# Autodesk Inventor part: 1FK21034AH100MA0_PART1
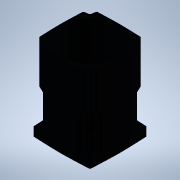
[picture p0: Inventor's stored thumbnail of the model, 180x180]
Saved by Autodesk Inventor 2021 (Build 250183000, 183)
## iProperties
Created: 2025-04
Part Number: 1FK21034AH100MA0_PART1
Material: Generic
Catalog Web Link: www.3dfindit.com
Description: -Servo synchronous motor
Document SubType Name: Modeling
Designer: psAdmin
Mass: 88.22 g
Surface Area: 399.791 cm^2
Volume: 88.22 cm^3
Density: 1 g/cm^3
Appearance: PSOLRGB-176-176-176
Category: PARTsolutions
Title: 1FK21034AH100MA0_PART1
Author: Cadenas PARTsolutions
Comments: Servo synchronous motor
Sending System: PARTsolutions
Preprocessor: ST-DEVELOPER v19.3
PSOL_IDENT_0: {$CADENAS_DATA/23d-libs/siemens_ag/_cat_/39/97/1fk21034ah100ma0.prj},213 {VTYP=3D},{NB=1FK21034AH100
PSOL_IDENT_1: MA0_PART1},{LINA=1FK21034AH100MA0_PART1},{NN=1FK21034AH100MA0_PART1},{NOPRJ=TRUE},{DATE=19.08.2025 1
PSOL_IDENT_2: 4:00:33},{GEOMDATE=30.07.2025 02:02:21},{VERSION=},{LINEID=10},{WBVAR=},{WBNUMERIC=}  {NB=1FK21034AH
PSOL_IDENT_3: 100MA0_PART1},{LINA=1FK21034AH100MA0_PART1},{KT=DUMMY},{PREVIEW=../../../_pool_/d3/78/p_d211_xx_0093
PSOL_IDENT_4: 4j.png},{DESCSHORT=SIMOTICS S-1FK2 HD, SINAMICS S210 3AC 400V-480V, 1.01 Nm, 4500 rpm},{DESCLONG=SIM
PSOL_IDENT_5: OTICS S-1FK2 HD servo motor M0=1.27 Nm; PN = 0.48 kW at nN=4500 rpm (380-480 V); PN = 0.3 kW at nN=2
PSOL_IDENT_6: 500 rpm (200-240 V); with holding brake; degree of protection IP64; cylindrical shaft D14 x 30 mm; a
PSOL_IDENT_7: bsolute encoder 22-bit + 12-bit multiturn (encoder AM22DQC); with OCC interface; plug size M17, rota
PSOL_IDENT_8: table; SIMOTICS S-1FK2 servomotorfor a wide range of uses in industrial environments. SIMOTICS S‑1FK
PSOL_IDENT_9: 2 servomotors are compact synchronous motors with a high dynamic performance that set themselves apa
PSOL_IDENT_10: rt as a result of their high power density, degree of protection and overload capability. The motors
PSOL_IDENT_11: are available in two variants: as High Dynamic variant (highest dynamic performance as a result of
PSOL_IDENT_12: the low intrinsic moment of inertia for applications demanding a high dynamic performance with low m
PSOL_IDENT_13: oved masses) - and as Compact variant (precise and stable closed-loop control for medium up to large
PSOL_IDENT_14: moved masses as a result of a medium intrinsic moment of inertia). SIMOTICSS‑1FK2 servomotors fully
PSOL_IDENT_15: exploit their strengths in a system with the SINAMICSS210 frequency converter and simple connection
PSOL_IDENT_16: using the one cable connection (OCC). Advantages include the short control and positioning times, f
PSOL_IDENT_17: ast and precise correction of disturbing quantities as well as stable control with a high dynamic pe
PSOL_IDENT_18: rformance. The servo motors can be configured to address a wide range of requirements. For example w
PSOL_IDENT_19: ith and without holding brake, IP64 or IP65 degree of protection, singleturn or multiturn absolute e
PSOL_IDENT_20: ncoders - to name just a few. Further, the servomotors are available in different shaft heights exte
PSOL_IDENT_21: nding from 20 to 100. A shaft sealing ring is available to achieve an IP65 degree of protection and
PSOL_IDENT_22: for subsequent mounting at the motor or as spare part. SIMOTICS - the optimum motor for each and eve
PSOL_IDENT_23: ry motion control application.},{INTNO=195125454019},{SUPPLIERALTNO=1FK2103-4AH10-0MA0},{MANUID=1FK2
PSOL_IDENT_24: 1034AH100MA0},{MANUNAME=Siemens},{MANUTYPEDESC=SYNCHRONOUS MOTOR 1FK2 HD 1,27 NM},{AAU732=SIMOTICS},
PSOL_IDENT_25: {AAO057=S-1FK2},{AAU734=SIMOTICS S-1FK2 HD servo motor M0=1.27 Nm; PN = 0.48 kW at nN=4500 rpm (380-
PSOL_IDENT_26: 480 V); PN = 0.3 kW at nN=2500 rpm (200-240 V); with holding brake; degree of protection IP64; cylin
PSOL_IDENT_27: drical shaft D14 x 30 mm; absolute encoder 22-bit + 12-bit multiturn (encoder AM22DQC); with OCC int
PSOL_IDENT_28: erface; plug size M17, rotatable;},{AAW338=SYNCHRONOUS MOTOR 1FK2 HD 1,27 NM},{AAO742=SIMOTICS},{AAO
PSOL_IDENT_29: 663=4034106444921},{NOCUPEROU=1},{PRICEQUANTITY=1},{QUANTITYMIN=1},{QUANTITYINT=1},{CTN=85015100},{C
PSOL_IDENT_30: OO=RO},{AAO676=1FK2103-4AH10-0MA0},{AAO677=Siemens AG},{ORDERUNIT=C62},{CONTENTUNIT=C62}
NB: 1FK21034AH100MA0_PART1
NT: Servo synchronous motor
NBSYN: $MANUID._PART1
LINA: 1FK21034AH100MA0_PART1
CATALOG: SIEMENS
PREVIEW: ../../../_pool_/d3/78/p_d211_xx_00934j.png
DESCSHORT: SIMOTICS S-1FK2 HD, SINAMICS S210 3AC 400V-480V, 1.01 Nm, 4500 rpm
DESCLONG: SIMOTICS S-1FK2 HD servo motor M0=1.27 Nm; PN = 0.48 kW at nN=4500 rpm (380-480 V); PN = 0.3 kW at nN=2500 rpm (200-240 V); with holding brake; degree of protec
INTNO: 195125454019
SUPPLIERALTNO: 1FK2103-4AH10-0MA0
MANUID: 1FK21034AH100MA0
MANUNAME: Siemens
MANUTYPEDESC: SYNCHRONOUS MOTOR 1FK2 HD 1,27 NM
AAU732: SIMOTICS
AAO057: S-1FK2
AAU734: SIMOTICS S-1FK2 HD servo motor M0=1.27 Nm; PN = 0.48 kW at nN=4500 rpm (380-480 V); PN = 0.3 kW at nN=2500 rpm (200-240 V); with holding brake; degree of protec
AAW338: SYNCHRONOUS MOTOR 1FK2 HD 1,27 NM
AAO742: SIMOTICS
AAO663: 4034106444921.0
NOCUPEROU: 1
PRICEQUANTITY: 1
QUANTITYMIN: 1
QUANTITYINT: 1
CTN: 85015100
COO: RO
ARTICLENO: 1FK21034AH100MA0_PART1
BOMINFO: 1FK21034AH100MA0_PART1
CREATOR: CADENAS GmbH
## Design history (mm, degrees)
feature "2025_04_17_15_09_00_0205"
node "ECLASS_CAX_IMPORTER_001_CP_0_XY"
node "ECLASS_CAX_IMPORTER_001_CP_0_YZ"
node "ECLASS_CAX_IMPORTER_001_CP_0_ZX"
node "ECLASS_CAX_IMPORTER_001_CP_0_X"
node "ECLASS_CAX_IMPORTER_001_CP_0_Y"
node "ECLASS_CAX_IMPORTER_001_CP_0_Z"
node "ECLASS_CAX_IMPORTER_001_CP_0_Center"
node "ECLASS_CAX_IMPORTER_001_CP_1_XY"
node "ECLASS_CAX_IMPORTER_001_CP_1_YZ"
node "ECLASS_CAX_IMPORTER_001_CP_1_ZX"
node "ECLASS_CAX_IMPORTER_001_CP_1_X"
node "ECLASS_CAX_IMPORTER_001_CP_1_Y"
node "ECLASS_CAX_IMPORTER_001_CP_1_Z"
node "ECLASS_CAX_IMPORTER_001_CP_1_Center"
body "Solid1"
